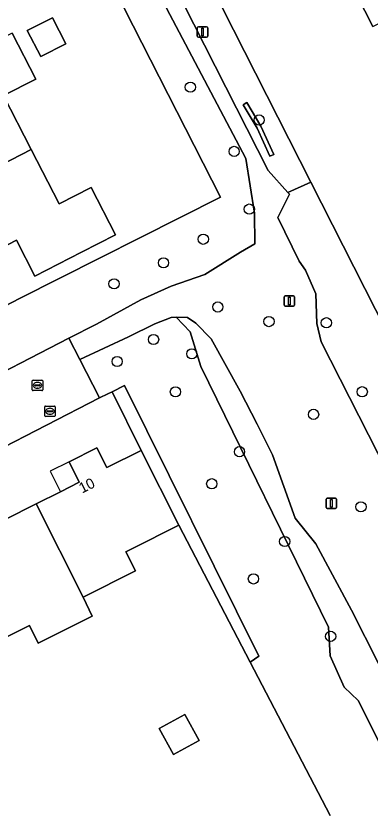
# Model space of a CAD drawing. Extents: x 162722 to 165104, y 384719 to 386284.
# Drawn here: x 163761.5 to 163795.3, y 385039.6 to 385115.6 of the extents above; entities that cross this region are included whole.
import ezdxf

# ---------------------------------------------------------------- set-up
doc = ezdxf.new("R2010")
doc.units = 0
for name, color, linetype in [('IMGEO_Boom', 7, 'Continuous'), ('IMGEO_Brandkraan', 7, 'Continuous'), ('IMGEO_Erf', 7, 'Continuous'), ('IMGEO_Groenvoorziening', 7, 'Continuous'), ('IMGEO_Haag', 7, 'Continuous'), ('IMGEO_Hek', 7, 'Continuous'), ('IMGEO_Kolk', 7, 'Continuous'), ('IMGEO_Lichtmast', 7, 'Continuous'), ('IMGEO_Pand', 7, 'Continuous'), ('IMGEO_Pand_nummerreeks', 7, 'Continuous'), ('IMGEO_Pand_overbouw', 7, 'Continuous'), ('IMGEO_Rijbaan_lokaal_open', 7, 'Continuous'), ('IMGEO_Voetpad_open', 7, 'Continuous')]:
    doc.layers.add(name, color=color, linetype=linetype)

msp = doc.modelspace()

# ---------------------------------------------------------------- linework, layer by layer
at = {"layer": 'IMGEO_Boom'}
for centre in [(163778.161, 385108.794), (163784.739, 385105.655), (163782.35, 385102.654), (163783.799, 385097.135), (163779.399, 385094.254), (163775.596, 385092.001), (163770.862, 385089.99), (163780.784, 385087.773), (163785.677, 385086.378), (163791.164, 385086.268), (163774.641, 385084.664), (163778.296, 385083.294), (163771.16, 385082.561), (163776.733, 385079.66), (163794.599, 385079.667), (163789.944, 385077.505), (163782.861, 385073.934), (163780.203, 385070.869), (163794.476, 385068.667), (163787.179, 385065.347), (163784.192, 385061.768), (163791.574, 385056.277)]:
    msp.add_circle(centre, 0.489, dxfattribs=at)
at = {"layer": 'IMGEO_Brandkraan'}
for p, q in [((163764.235, 385077.377), (163764.235, 385078.229)), ((163764.31, 385078.303), (163765.162, 385078.303)), ((163764.494, 385077.797), (163764.494, 385077.809)), ((163764.932, 385077.76), (163764.534, 385077.76)), ((163764.537, 385077.846), (163764.935, 385077.846)), ((163764.723, 385078.083), (163764.748, 385078.083)), ((163764.978, 385077.809), (163764.978, 385077.797)), ((163765.236, 385078.229), (163765.236, 385077.377)), ((163765.162, 385077.303), (163764.31, 385077.303)), ((163764.746, 385077.523), (163764.721, 385077.523))]:
    msp.add_line(p, q, dxfattribs=at)
for points in [[(163764.235, 385077.377), (163764.235, 385078.229)], [(163764.31, 385078.303), (163765.162, 385078.303)], [(163765.236, 385078.229), (163765.236, 385077.377)], [(163765.162, 385077.303), (163764.31, 385077.303)]]:
    msp.add_lwpolyline(points, dxfattribs=at)
for centre, radius, start, end in [((163764.312, 385078.227), 0.0765, 91.55205, 178.44795), ((163764.312, 385078.227), 0.0765, 91.55205, 178.44795), ((163764.534, 385077.806), 0.0403, 85.87752, 175.75265), ((163764.531, 385077.796), 0.0366, 178.93798, 274.71019), ((163764.935, 385077.803), 0.043, 264.86636, 352.45326), ((163764.939, 385077.808), 0.0386, 1.73085, 96.63898), ((163765.16, 385078.227), 0.0765, 1.55205, 88.44795), ((163765.16, 385078.227), 0.0765, 1.55205, 88.44795), ((163764.312, 385077.379), 0.0765, 181.55205, 268.44795), ((163764.312, 385077.379), 0.0765, 181.55205, 268.44795), ((163765.16, 385077.379), 0.0765, 271.55205, 358.44795), ((163765.16, 385077.379), 0.0765, 271.55205, 358.44795)]:
    msp.add_arc(centre, radius, start, end, dxfattribs=at)
for centre, major_axis, ratio, start_param, end_param in [((163764.722, 385077.803), (-0.387, 0.002), 0.722429, 4.712389, 7.853982), ((163764.747, 385077.803), (-0.39, 0.002), 0.717154, 1.570796, 4.712389)]:
    msp.add_ellipse(centre, major_axis=major_axis, ratio=ratio, start_param=start_param, end_param=end_param, dxfattribs=at)
at = {"layer": 'IMGEO_Erf'}
for points in [[(163777.061, 385181.644), (163776.532, 385181.386), (163770.303, 385178.196), (163758.67, 385172.275), (163773.324, 385139.627), (163770.253, 385138.072), (163770.819, 385136.953), (163780.19, 385118.446), (163789.688, 385099.725), (163809.284, 385061.102), (163812.187, 385062.627), (163827.853, 385070.567), (163835.892, 385074.67), (163835.122, 385076.225), (163833.369, 385079.662), (163826.65, 385092.98), (163823.907, 385098.369), (163817.57, 385111.145), (163814.72, 385116.503), (163808.329, 385129.137), (163805.546, 385134.581), (163799.125, 385147.174), (163797.047, 385151.214), (163789.743, 385165.63)], [(163720.799, 385149.656), (163733.386, 385124.897), (163735.22, 385121.265), (163741.754, 385108.434), (163745.114, 385101.827), (163751.491, 385089.235), (163753.386, 385085.536), (163753.931, 385084.458), (163761.818, 385088.577), (163781.027, 385098.268), (163760.145, 385139.341), (163746.528, 385166.095)], [(163795.605, 385114.608), (163791.032, 385123.624)], [(163761.114, 385113.963), (163763.374, 385109.57), (163760.299, 385107.988), (163762.948, 385102.838), (163765.629, 385097.626), (163768.67, 385099.19), (163770.989, 385094.68), (163767.749, 385093.014), (163763.302, 385090.726), (163761.536, 385094.159), (163755.592, 385091.102)], [(163760.451, 385067.447), (163763.416, 385068.936), (163765.741, 385070.104), (163767.541, 385071.008), (163766.556, 385072.968), (163769.227, 385074.31), (163770.179, 385072.414), (163773.447, 385074.055), (163770.698, 385079.675), (163770.256, 385079.462), (163769.461, 385079.078), (163759.29, 385073.861)], [(163791.526, 385039.145), (163783.871, 385053.812), (163777.042, 385066.898), (163772.574, 385064.655), (163771.999, 385064.366), (163772.909, 385062.553), (163767.9, 385060.037), (163768.76, 385058.212), (163763.622, 385055.631), (163762.769, 385057.329), (163758.028, 385054.947), (163757.832, 385054.849), (163756.951, 385056.602), (163752.423, 385054.328), (163753.315, 385052.554), (163748.113, 385049.942), (163747.123, 385051.691), (163742.548, 385049.393), (163743.452, 385047.594), (163742.514, 385047.123), (163738.045, 385044.879), (163743.285, 385034.094)]]:
    msp.add_lwpolyline(points, dxfattribs=at)
for points in [[(163762.569, 385114.203), (163764.977, 385115.441), (163766.255, 385112.955), (163763.848, 385111.717)], [(163775.181, 385047.453), (163777.622, 385048.801), (163778.991, 385046.322), (163776.55, 385044.974)]]:
    msp.add_lwpolyline(points, close=True, dxfattribs=at)
at = {"layer": 'IMGEO_Groenvoorziening'}
for points in [[(163770.819, 385136.953), (163770.253, 385138.072), (163773.324, 385139.627), (163758.67, 385172.275), (163753.89, 385169.842), (163754.236, 385169.136), (163765.683, 385145.787), (163768.37, 385134.799), (163785.613, 385100.832), (163787.475, 385098.737), (163789.688, 385099.725), (163780.19, 385118.446)], [(163751.75, 385168.753), (163746.528, 385166.095), (163760.145, 385139.341), (163781.027, 385098.268), (163761.818, 385088.577), (163753.931, 385084.458), (163756.413, 385079.553), (163766.533, 385084.8), (163769.171, 385086.138), (163773.434, 385088.46), (163776.32, 385089.774), (163779.555, 385090.879), (163782.967, 385093.011), (163784.312, 385093.815), (163784.3, 385096.739), (163783.48, 385101.975), (163766.464, 385134.202), (163763.257, 385146.803)], [(163785.768, 385102.203), (163784.554, 385104.874), (163783.206, 385107.112), (163783.548, 385107.318), (163784.908, 385105.06), (163786.132, 385102.369)], [(163783.206, 385107.112), (163784.554, 385104.874), (163785.768, 385102.203), (163786.132, 385102.369), (163784.908, 385105.06), (163783.548, 385107.318)], [(163789.688, 385099.725), (163787.475, 385098.737), (163787.639, 385098.552), (163786.539, 385096.347), (163788.574, 385092.153), (163789.177, 385091.301), (163790.172, 385089.019), (163790.245, 385086.186), (163790.668, 385084.443), (163796.093, 385073.79), (163796.708, 385072.045), (163798.328, 385068.981), (163799.295, 385065.619), (163800.413, 385061.05), (163801.25, 385058.342), (163801.488, 385057.858), (163802.175, 385057.526), (163802.941, 385057.701), (163806.431, 385059.323), (163806.318, 385059.544), (163809.284, 385061.102)], [(163776.799, 385086.81), (163778.131, 385085.393), (163779.162, 385082.093), (163791.359, 385057.157), (163791.535, 385054.401), (163792.881, 385051.428), (163794.209, 385050.139), (163807.026, 385024.596), (163808.566, 385025.713), (163809.035, 385026.84), (163808.847, 385028.154), (163805.421, 385035.138), (163798.727, 385048.566), (163793.575, 385058.788), (163790.143, 385065.128), (163788.181, 385067.57), (163786.027, 385073.647), (163785.482, 385074.719), (163784.543, 385076.561), (163782.934, 385079.72), (163780.143, 385084.723), (163778.682, 385086.223), (163777.874, 385086.761)]]:
    msp.add_lwpolyline(points, close=True, dxfattribs=at)
for points in [[(163796.093, 385073.79), (163790.668, 385084.443), (163790.245, 385086.186), (163790.172, 385089.019), (163789.177, 385091.301), (163788.574, 385092.153), (163786.539, 385096.347), (163787.639, 385098.552), (163787.475, 385098.737), (163785.613, 385100.832), (163768.37, 385134.799)], [(163766.464, 385134.202), (163783.48, 385101.975), (163784.3, 385096.739), (163784.312, 385093.815), (163782.967, 385093.011), (163779.555, 385090.879), (163776.32, 385089.774), (163773.434, 385088.46), (163769.171, 385086.138), (163766.533, 385084.8), (163767.576, 385082.761), (163772.247, 385084.935), (163774.778, 385086.177), (163776.334, 385086.766), (163776.799, 385086.81), (163777.874, 385086.761), (163778.682, 385086.223), (163780.143, 385084.723), (163782.934, 385079.72), (163784.543, 385076.561), (163785.482, 385074.719), (163786.027, 385073.647), (163788.181, 385067.57), (163790.143, 385065.128), (163793.575, 385058.788), (163798.727, 385048.566)], [(163807.026, 385024.596), (163794.209, 385050.139), (163792.881, 385051.428), (163791.535, 385054.401), (163791.359, 385057.157), (163779.162, 385082.093), (163778.131, 385085.393), (163776.799, 385086.81), (163776.334, 385086.766), (163774.778, 385086.177), (163772.247, 385084.935), (163767.576, 385082.761), (163769.461, 385079.078), (163770.256, 385079.462), (163770.698, 385079.675), (163771.877, 385080.263), (163784.704, 385054.386), (163783.871, 385053.812), (163791.526, 385039.145)]]:
    msp.add_lwpolyline(points, dxfattribs=at)
at = {"layer": 'IMGEO_Haag'}
msp.add_lwpolyline([(163783.206, 385107.112), (163784.554, 385104.874), (163785.768, 385102.203), (163786.132, 385102.369), (163784.908, 385105.06), (163783.548, 385107.318)], close=True, dxfattribs=at)
at = {"layer": 'IMGEO_Hek'}
msp.add_lwpolyline([(163777.042, 385066.898), (163783.871, 385053.812)], dxfattribs=at)
at = {"layer": 'IMGEO_Kolk'}
for p, q in [((163763.041, 385079.852), (163763.041, 385080.704)), ((163763.116, 385080.778), (163763.968, 385080.778)), ((163764.042, 385080.704), (163764.042, 385079.852)), ((163763.3, 385080.272), (163763.3, 385080.284)), ((163763.738, 385080.235), (163763.34, 385080.235)), ((163763.343, 385080.321), (163763.741, 385080.321)), ((163763.552, 385079.998), (163763.527, 385079.998)), ((163763.529, 385080.558), (163763.554, 385080.558)), ((163763.784, 385080.284), (163763.784, 385080.272)), ((163763.968, 385079.778), (163763.116, 385079.778))]:
    msp.add_line(p, q, dxfattribs=at)
for points in [[(163763.041, 385079.852), (163763.041, 385080.704)], [(163763.116, 385080.778), (163763.968, 385080.778)], [(163764.042, 385080.704), (163764.042, 385079.852)], [(163763.968, 385079.778), (163763.116, 385079.778)]]:
    msp.add_lwpolyline(points, dxfattribs=at)
for centre, radius, start, end in [((163763.118, 385080.702), 0.0765, 91.55205, 178.44795), ((163763.118, 385080.702), 0.0765, 91.55205, 178.44795), ((163763.966, 385080.702), 0.0765, 1.55205, 88.44795), ((163763.966, 385080.702), 0.0765, 1.55205, 88.44795), ((163763.34, 385080.281), 0.0403, 85.87752, 175.75265), ((163763.337, 385080.271), 0.0366, 178.93798, 274.71019), ((163763.741, 385080.278), 0.043, 264.86636, 352.45326), ((163763.745, 385080.283), 0.0386, 1.73085, 96.63898), ((163763.118, 385079.854), 0.0765, 181.55205, 268.44795), ((163763.118, 385079.854), 0.0765, 181.55205, 268.44795), ((163763.966, 385079.854), 0.0765, 271.55205, 358.44795), ((163763.966, 385079.854), 0.0765, 271.55205, 358.44795)]:
    msp.add_arc(centre, radius, start, end, dxfattribs=at)
for centre, major_axis, ratio, start_param, end_param in [((163763.528, 385080.278), (-0.387, 0.002), 0.722429, 4.712389, 7.853982), ((163763.553, 385080.278), (-0.39, 0.002), 0.717154, 1.570796, 4.712389)]:
    msp.add_ellipse(centre, major_axis=major_axis, ratio=ratio, start_param=start_param, end_param=end_param, dxfattribs=at)
at = {"layer": 'IMGEO_Lichtmast'}
for p, q in [((163778.826, 385113.674), (163778.826, 385114.474)), ((163778.826, 385114.474), (163778.826, 385113.674)), ((163778.926, 385114.574), (163779.716, 385114.574)), ((163779.716, 385114.574), (163778.926, 385114.574)), ((163779.816, 385114.474), (163779.816, 385113.674)), ((163779.816, 385113.674), (163779.816, 385114.474)), ((163779.716, 385113.574), (163778.926, 385113.574)), ((163778.926, 385113.574), (163779.716, 385113.574)), ((163787.139, 385087.944), (163787.139, 385088.744)), ((163787.139, 385088.744), (163787.139, 385087.944)), ((163787.239, 385088.844), (163788.029, 385088.844)), ((163788.029, 385088.844), (163787.239, 385088.844)), ((163788.129, 385088.744), (163788.129, 385087.944)), ((163788.129, 385087.944), (163788.129, 385088.744)), ((163788.029, 385087.844), (163787.239, 385087.844)), ((163787.239, 385087.844), (163788.029, 385087.844)), ((163791.156, 385068.602), (163791.156, 385069.402)), ((163791.156, 385069.402), (163791.156, 385068.602)), ((163791.256, 385069.502), (163792.046, 385069.502)), ((163792.046, 385069.502), (163791.256, 385069.502)), ((163792.146, 385069.402), (163792.146, 385068.602)), ((163792.146, 385068.602), (163792.146, 385069.402)), ((163792.046, 385068.502), (163791.256, 385068.502)), ((163791.256, 385068.502), (163792.046, 385068.502))]:
    msp.add_line(p, q, dxfattribs=at)
for points in [[(163779.246, 385114.449), (163779.396, 385114.449), (163779.396, 385113.699), (163779.246, 385113.699), (163779.246, 385114.449)], [(163787.559, 385088.719), (163787.709, 385088.719), (163787.709, 385087.969), (163787.559, 385087.969), (163787.559, 385088.719)], [(163791.576, 385069.377), (163791.726, 385069.377), (163791.726, 385068.627), (163791.576, 385068.627), (163791.576, 385069.377)]]:
    msp.add_lwpolyline(points, dxfattribs=at)
for centre, start, end in [((163778.926, 385114.474), 90, 180), ((163778.926, 385114.474), 90, 180), ((163779.716, 385114.474), 0, 90), ((163779.716, 385114.474), 360, 90), ((163778.926, 385113.674), 180, 270), ((163778.926, 385113.674), 180, 270), ((163779.716, 385113.674), 270, 0), ((163779.716, 385113.674), 270, 0), ((163787.239, 385088.744), 90, 180), ((163787.239, 385088.744), 90, 180), ((163788.029, 385088.744), 0, 90), ((163788.029, 385088.744), 360, 90), ((163787.239, 385087.944), 180, 270), ((163787.239, 385087.944), 180, 270), ((163788.029, 385087.944), 270, 0), ((163788.029, 385087.944), 270, 0), ((163791.256, 385069.402), 90, 180), ((163791.256, 385069.402), 90, 180), ((163792.046, 385069.402), 0, 90), ((163792.046, 385069.402), 360, 90), ((163791.256, 385068.602), 180, 270), ((163791.256, 385068.602), 180, 270), ((163792.046, 385068.602), 270, 0), ((163792.046, 385068.602), 270, 0)]:
    msp.add_arc(centre, 0.1, start, end, dxfattribs=at)
at = {"layer": 'IMGEO_Pand'}
for points in [[(163807.834, 385120.811), (163807.54, 385121.392), (163807.986, 385121.618), (163806.631, 385124.291), (163806.185, 385124.065), (163804.739, 385126.915), (163804.935, 385127.015), (163804.799, 385127.282), (163798.118, 385123.893), (163796.775, 385126.542), (163791.032, 385123.624), (163795.605, 385114.608)], [(163762.569, 385114.203), (163763.848, 385111.717), (163766.255, 385112.955), (163764.977, 385115.441)], [(163753.267, 385109.928), (163754.941, 385106.674), (163749.122, 385103.68), (163752.357, 385097.391), (163762.948, 385102.838), (163760.299, 385107.988), (163763.374, 385109.57), (163761.114, 385113.963)], [(163752.357, 385097.391), (163755.592, 385091.102), (163761.536, 385094.159), (163763.302, 385090.726), (163767.749, 385093.014), (163770.989, 385094.68), (163768.67, 385099.19), (163765.629, 385097.626), (163762.948, 385102.838)], [(163773.447, 385074.055), (163770.179, 385072.414), (163769.227, 385074.31), (163766.556, 385072.968), (163767.541, 385071.008), (163765.741, 385070.104), (163763.416, 385068.936), (163767.9, 385060.037), (163772.909, 385062.553), (163771.999, 385064.366), (163772.574, 385064.655), (163777.042, 385066.898)], [(163763.416, 385068.936), (163760.451, 385067.447), (163759.469, 385069.404), (163756.732, 385068.029), (163757.701, 385066.099), (163755.865, 385065.177), (163753.284, 385063.881), (163756.951, 385056.602), (163757.832, 385054.849), (163758.028, 385054.947), (163762.769, 385057.329), (163763.622, 385055.631), (163768.76, 385058.212), (163767.9, 385060.037)], [(163775.181, 385047.453), (163776.55, 385044.974), (163778.991, 385046.322), (163777.622, 385048.801)]]:
    msp.add_lwpolyline(points, close=True, dxfattribs=at)
at = {"layer": 'IMGEO_Pand_overbouw'}
msp.add_lwpolyline([(163766.556, 385072.968), (163764.756, 385072.064), (163765.741, 385070.104), (163767.541, 385071.008)], close=True, dxfattribs=at)
at = {"layer": 'IMGEO_Rijbaan_lokaal_open'}
msp.add_lwpolyline([(163767.576, 385082.761), (163766.533, 385084.8), (163756.413, 385079.553), (163759.29, 385073.861), (163769.461, 385079.078)], close=True, dxfattribs=at)
at = {"layer": 'IMGEO_Voetpad_open'}
msp.add_lwpolyline([(163784.704, 385054.386), (163771.877, 385080.263), (163770.698, 385079.675), (163773.447, 385074.055), (163777.042, 385066.898), (163783.871, 385053.812)], close=True, dxfattribs=at)

# ---------------------------------------------------------------- texts
at = {"layer": 'IMGEO_Pand_nummerreeks'}
msp.add_text('10', height=1, rotation=26.67119, dxfattribs=at).set_placement((163767.809, 385069.927))

doc.saveas('drawing.dxf')
